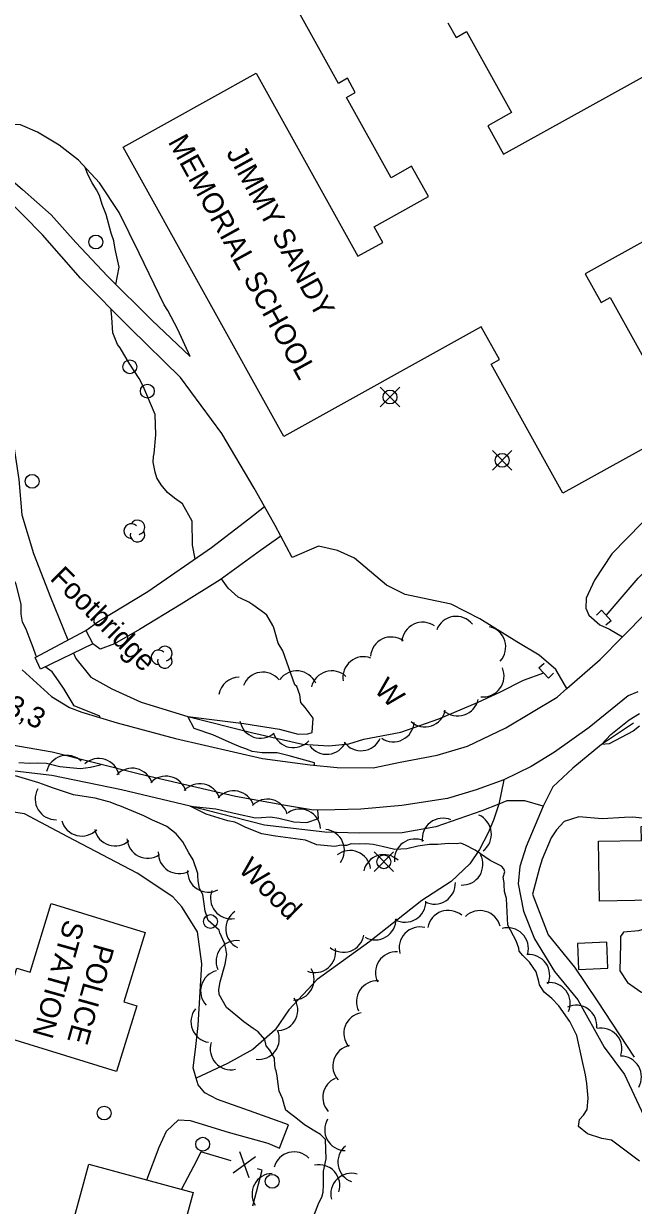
# Model space of a CAD drawing. Extents: x 642515 to 647219, y 6080136 to 6084356.
# Drawn here: x 643658.8 to 643746.7, y 6081698.7 to 6081869.2 of the extents above; entities that cross this region are included whole.
import ezdxf

# ---------------------------------------------------------------- set-up
doc = ezdxf.new("R2010")
doc.units = 0
for name, color, linetype in [('Level 1', 7, 'Continuous'), ('Level 19', 7, 'Continuous'), ('Level 2', 7, 'Continuous'), ('Level 21', 7, 'Continuous'), ('Level 22', 7, 'Continuous'), ('Level 26', 7, 'Continuous'), ('Level 3', 7, 'Continuous'), ('Level 31', 7, 'Continuous'), ('Level 36', 7, 'Continuous'), ('Level 37', 7, 'Continuous'), ('Level 4', 7, 'Continuous'), ('Level 44', 7, 'Continuous'), ('Level 52', 7, 'Continuous')]:
    doc.layers.add(name, color=color, linetype=linetype)

msp = doc.modelspace()

# ---------------------------------------------------------------- linework, layer by layer
at = {"layer": 'Level 1'}
for points in [[(643672.06, 6081831.55), (643672.52, 6081834.03), (643671.95, 6081836.65), (643671.76, 6081837.86), (643671.39, 6081838.95), (643670.65, 6081841.63), (643670.06, 6081843.06), (643669.67, 6081844.39), (643669.27, 6081845.19), (643668.66, 6081846.19), (643668.08, 6081847.3), (643667.63, 6081848.44)], [(643683.49, 6081791.99), (643683.13, 6081793.96), (643683.04, 6081797.42), (643681.67, 6081799.91), (643680.51, 6081800.72), (643679.51, 6081801.53), (643678.57, 6081802.67), (643677.96, 6081803.66), (643677.72, 6081804.47), (643677.44, 6081805.92), (643677.48, 6081806.71), (643677.58, 6081807.15), (643677.84, 6081809.85), (643677.73, 6081812.8), (643676, 6081816.89), (643675.42, 6081818), (643673.99, 6081820.18), (643673.21, 6081821.48), (643672.68, 6081822.4), (643672.29, 6081822.89), (643671.61, 6081824.55), (643671.45, 6081826.79), (643671.36, 6081827.77), (643671.4, 6081827.96)], [(643700.71, 6081762.19), (643700.68, 6081762.54), (643697.07, 6081763.57), (643695.33, 6081763.99), (643695.17, 6081763.98), (643693.14, 6081763.99), (643691.73, 6081764.19), (643690.79, 6081764.58), (643690.1, 6081764.82), (643688.83, 6081765.34), (643686.02, 6081766.57), (643683.37, 6081767.49), (643682.41, 6081769.24), (643690.49, 6081768.21), (643695.64, 6081767.38), (643698.35, 6081766.7), (643699.75, 6081766.73), (643700.38, 6081766.92), (643700.51, 6081768.98), (643699.36, 6081770.53), (643698.72, 6081771.25), (643698.58, 6081772.35), (643698.16, 6081773.54), (643697.87, 6081773.81), (643696.14, 6081778.72), (643695.48, 6081779.83), (643695.14, 6081781.03), (643694.85, 6081782.04), (643694.68, 6081782.35), (643693.84, 6081783.84), (643693.55, 6081784.1), (643691.81, 6081785.35), (643691.23, 6081785.71), (643690.12, 6081786.24), (643689.71, 6081786.46), (643688.25, 6081787.76), (643687.31, 6081789.09)], [(643733.05, 6081731.01), (643732.68, 6081732.39), (643731.7, 6081733.78), (643730.74, 6081734.76), (643730.22, 6081735.37), (643730.15, 6081735.81), (643729.79, 6081736.88), (643728.59, 6081739.13), (643728.41, 6081742.99), (643728.1, 6081744.01), (643728.08, 6081744.94), (643728.06, 6081745.26), (643728.06, 6081745.26), (643727.89, 6081746.07), (643728.13, 6081746.84), (643727.99, 6081747.26), (643727.65, 6081747.64), (643726.06, 6081748.46), (643723.86, 6081749.96), (643722.47, 6081750.67), (643721.82, 6081750.95), (643721.22, 6081750.88), (643719.98, 6081750.93), (643718.47, 6081750.77), (643717.27, 6081750.79), (643715.61, 6081750.54), (643714.03, 6081750.14), (643712.31, 6081750.07), (643710.47, 6081750.47), (643709.16, 6081750.79), (643708.1, 6081750.88), (643707.22, 6081750.82), (643705.97, 6081750.86), (643705.3, 6081750.62), (643704.78, 6081750.62), (643704.57, 6081750.65), (643703.62, 6081750.5), (643701.06, 6081750.7), (643699.41, 6081751.39), (643695.06, 6081751.95), (643693.1, 6081752.31), (643691.74, 6081752.82), (643690.7, 6081753.28), (643689.74, 6081753.74), (643689.2, 6081753.98), (643688.22, 6081754.16), (643685.06, 6081755.12), (643682.77, 6081756.28), (643686.46, 6081755.92), (643689.53, 6081755.2), (643692.19, 6081754.61), (643693.07, 6081754.66)], [(643693.07, 6081754.66), (643694.35, 6081754.75), (643695.54, 6081754.55), (643697.74, 6081754.05), (643699.61, 6081753.93), (643701.26, 6081754.52), (643701.17, 6081755.74)], [(643748.05, 6081754.55), (643746.51, 6081754.7), (643746.51, 6081754.7), (643745.4, 6081754.64), (643742.21, 6081754.47), (643738.84, 6081754.77), (643736.72, 6081754.1), (643735.59, 6081752.86), (643734.85, 6081751.72), (643733.56, 6081748.66), (643733.15, 6081747.38), (643732.14, 6081743.62), (643734.4, 6081737.73), (643738.18, 6081733.07), (643741.49, 6081728.21), (643746.79, 6081720.11)], [(643747.58, 6081705.11), (643743.55, 6081708.1), (643742.12, 6081708.37), (643740.06, 6081709.04), (643738.79, 6081710.09), (643738.92, 6081711.1), (643739.48, 6081711.74), (643740.03, 6081712.54), (643740.16, 6081714.16), (643739.97, 6081716.28), (643739.77, 6081717.52), (643739.36, 6081719.47), (643738.54, 6081723.2), (643737.51, 6081725.22), (643735.95, 6081727.5), (643734.91, 6081728.56), (643733.84, 6081729.49), (643733.16, 6081730.53), (643733.05, 6081731.01)]]:
    msp.add_lwpolyline(points, dxfattribs=at)
at = {"layer": 'Level 19'}
for points in [[(643679.03, 6081828.61), (643675.43, 6081836.08), (643672.53, 6081841.95), (643669.71, 6081846.21), (643666.67, 6081849.46), (643663.89, 6081851.64), (643660.77, 6081853.52), (643658.3, 6081854.59), (643656.61, 6081854.67), (643654.77, 6081854.41), (643652.88, 6081853.67), (643650.76, 6081852.08), (643654.19, 6081849.01), (643658.58, 6081845.24), (643662.73, 6081841.61), (643666.29, 6081837.59), (643670.87, 6081832.74), (643677.22, 6081826.38), (643682.78, 6081821.18), (643680.99, 6081825.06), (643679.55, 6081827.79), (643679.03, 6081828.61)], [(643737.09, 6081773.25), (643735.53, 6081776.01), (643733.12, 6081778.09), (643729.88, 6081780), (643724.54, 6081783.33), (643720.4, 6081785.44), (643716.28, 6081786.31), (643713.76, 6081786.82), (643711.07, 6081788.16), (643706.46, 6081792.05), (643704.03, 6081793.16), (643701.3, 6081793.78), (643697.48, 6081792.18), (643695.86, 6081795.26), (643695.05, 6081796.78), (643693.51, 6081799.5), (643692.01, 6081802.16), (643687.34, 6081810.05), (643681.38, 6081818.12), (643674.1, 6081825.23), (643666.97, 6081832.44), (643661.47, 6081838.72), (643655.92, 6081844.36)], [(643667.7, 6081781.62), (643669.6, 6081782.96), (643676.66, 6081787.25), (643685.83, 6081793.61), (643691.22, 6081797.73), (643693.51, 6081799.5)], [(643750.11, 6081799.36), (643743.57, 6081792.69), (643741.08, 6081788.91), (643739.86, 6081786.28), (643739.82, 6081784.88), (643740.28, 6081783.86), (643741.84, 6081782.46), (643743.25, 6081781.81), (643745.13, 6081780.73)], [(643695.86, 6081795.26), (643692.92, 6081793.18), (643687.12, 6081788.95), (643681.49, 6081785.41), (643675.47, 6081781.78), (643671.85, 6081779.71), (643669.77, 6081778.92), (643668.72, 6081779.71)], [(643754.49, 6081745.61), (643755.21, 6081745.04), (643755.61, 6081743.77), (643754.74, 6081742.09), (643753, 6081739.81), (643750.16, 6081739.13), (643747.44, 6081738.33), (643745.26, 6081738.13), (643744.85, 6081737.5), (643744.83, 6081736.44), (643744.74, 6081732.54), (643745.86, 6081730.85), (643747.77, 6081729.53), (643752.19, 6081727.66), (643755.21, 6081725.47)]]:
    msp.add_lwpolyline(points, dxfattribs=at)
at = {"layer": 'Level 2'}
for points in [[(643660.62, 6081777.87), (643660.53, 6081778.09), (643660.15, 6081779.17), (643659.55, 6081780.68), (643659.1, 6081781.83), (643658.57, 6081782.83), (643658.42, 6081784), (643658.39, 6081785.38), (643657.68, 6081788.33), (643656.63, 6081790.24), (643654.47, 6081799.58), (643653.99, 6081801.96), (643653.52, 6081803.94), (643653.25, 6081805.3), (643652.71, 6081808.03), (643651.56, 6081814.08), (643651.3, 6081815.21), (643650.42, 6081819.97), (643648.85, 6081824.89), (643646.7, 6081832.34), (643643.63, 6081838.45), (643641.72, 6081840.59), (643641.66, 6081841.43)], [(643669.72, 6081769.09), (643669.72, 6081769.26), (643666.05, 6081770.79), (643664.61, 6081773.19), (643663.79, 6081774.37), (643662.85, 6081775.66), (643661.84, 6081776.39)], [(643747.56, 6081767.82), (643746.64, 6081767.12), (643744.93, 6081766.21), (643743.21, 6081765.31), (643742.11, 6081765.18), (643743.46, 6081766.63), (643746.1, 6081768.76), (643747.57, 6081769.66)], [(643658.06, 6081762.59), (643659.63, 6081762.49), (643660.72, 6081762.53), (643662.05, 6081762.49), (643663.97, 6081762.02), (643665.43, 6081761.87), (643666.97, 6081761.73), (643668.4, 6081761.91), (643669.83, 6081762.24), (643669.83, 6081762.32)], [(643695.32, 6081717.39), (643695.19, 6081718.11), (643695.1, 6081718.34), (643694.98, 6081718.9), (643694.91, 6081719.94), (643694.27, 6081721.1), (643693.74, 6081721.71), (643693.52, 6081722.66), (643692.6, 6081723.77), (643691.88, 6081724.24), (643690.53, 6081725.2), (643689.38, 6081726.13), (643688.02, 6081727.25), (643686.96, 6081729.15), (643686.91, 6081729.87), (643687.12, 6081730.97), (643687.83, 6081733.51), (643688.06, 6081734.89), (643687.92, 6081735.76), (643687.71, 6081736.55), (643687.04, 6081738.04), (643686.94, 6081738.43), (643685.35, 6081739.81), (643684.94, 6081741.15), (643684.79, 6081742.19), (643684.62, 6081743.55), (643684.12, 6081744.44), (643683.92, 6081745.51), (643683.87, 6081746.31), (643683.89, 6081746.59), (643683.19, 6081748.56), (643682.56, 6081749.56), (643681.69, 6081751.15), (643680.73, 6081752.29), (643679.41, 6081753.37), (643678.37, 6081753.83), (643677.33, 6081754.28), (643676.08, 6081754.92), (643672.65, 6081756.34), (643672.28, 6081756.44), (643671.21, 6081756.85), (643670.84, 6081756.95), (643669.08, 6081757.44), (643668.1, 6081757.61), (643665.95, 6081757.91), (643662.9, 6081758.92), (643662, 6081759.26), (643660.96, 6081759.64), (643657.56, 6081760.66)], [(643700.6, 6081697.2), (643701.35, 6081699.09), (643701.74, 6081699.88), (643701.93, 6081700.62), (643702.02, 6081701.67), (643702.01, 6081703.64), (643702.37, 6081705.43), (643702.3, 6081708.2), (643701.57, 6081708.92), (643700.73, 6081709.43), (643699.26, 6081710.34), (643698.03, 6081711.34), (643697.26, 6081711.93), (643696.58, 6081712.45), (643696.38, 6081713.08), (643696.07, 6081714.11), (643695.59, 6081715.2), (643695.42, 6081716.56), (643695.32, 6081717.39)]]:
    msp.add_lwpolyline(points, dxfattribs=at)
at = {"layer": 'Level 21'}
for points in [[(643658.54, 6081775.96), (643662.77, 6081772.11), (643665.39, 6081770.52), (643667.16, 6081769.86), (643672.26, 6081768.32), (643680.65, 6081766.04), (643693.19, 6081763.18), (643700.07, 6081762.26), (643703.99, 6081761.86), (643709.14, 6081761.81), (643713.07, 6081762.62), (643718.37, 6081763.65), (643722.76, 6081764.96), (643728.28, 6081767.61), (643735.68, 6081772.01), (643737.09, 6081773.25), (643741.89, 6081777.46), (643745.13, 6081780.73), (643748.6, 6081784.22), (643756.35, 6081793.16), (643766.55, 6081805.08), (643776.58, 6081816.72), (643784.32, 6081827.51)], [(643747.33, 6081772.79), (643745.95, 6081772.2), (643740.33, 6081767.66), (643735.34, 6081764.08), (643731.96, 6081762.02), (643728, 6081760.09), (643724.02, 6081758.64), (643719.87, 6081757.42), (643713.29, 6081756.4), (643707.37, 6081755.85), (643703.64, 6081755.77)], [(643703.64, 6081755.77), (643700.54, 6081755.73), (643696.51, 6081756.41), (643689.31, 6081757.71), (643675.46, 6081760.91), (643662.87, 6081764.07), (643657.04, 6081765.09)]]:
    msp.add_lwpolyline(points, dxfattribs=at)
at = {"layer": 'Level 22'}
msp.add_lwpolyline([(643728, 6081760.09), (643727.29, 6081756.59), (643726.5, 6081754.27), (643725.75, 6081752.43), (643724.52, 6081750.04), (643723.11, 6081747.97), (643720.41, 6081745.42), (643716.18, 6081742.68), (643708.66, 6081736.76), (643701.07, 6081731.29), (643697, 6081726.9), (643695.01, 6081724.02), (643691.81, 6081721.22), (643688.15, 6081719.2), (643685.06, 6081717.75), (643683.65, 6081717.07)], dxfattribs=at)
at = {"layer": 'Level 26'}
for p, q in [((643742.09, 6081784.55), (643741.35, 6081783.87)), ((643742.09, 6081784.55), (643743.47, 6081783.05)), ((643743.47, 6081783.05), (643742.73, 6081782.39)), ((643733.07, 6081776.26), (643733.81, 6081776.94)), ((643734.45, 6081774.78), (643733.07, 6081776.26)), ((643734.45, 6081774.78), (643735.19, 6081775.46))]:
    msp.add_line(p, q, dxfattribs=at)
msp.add_lwpolyline([(643668.72, 6081779.71), (643661.18, 6081776.08), (643660.4, 6081777.75), (643667.7, 6081781.62), (643668.72, 6081779.71)], dxfattribs=at)
at = {"layer": 'Level 31'}
for points in [[(643724.72, 6081825.43), (643696.26, 6081809.64), (643673.11, 6081851.37), (643692.31, 6081862.03), (643706.97, 6081835.61), (643710.56, 6081837.6), (643709.29, 6081839.87), (643717.13, 6081844.22), (643714.7, 6081848.59), (643711.74, 6081846.95), (643705.31, 6081858.53), (643706.59, 6081859.24), (643705.46, 6081861.29), (643704.15, 6081860.56), (643693.83, 6081879.17)], [(643719.94, 6081869.29), (643721.11, 6081867.19), (643722.63, 6081868.03), (643729.12, 6081856.33), (643725.68, 6081854.42), (643727.94, 6081850.34), (643749.38, 6081862.24), (643750.01, 6081861.11), (643753.38, 6081862.98), (643761.04, 6081849.17), (643757.62, 6081847.27), (643759.42, 6081844.02), (643739.76, 6081833.1), (643742.06, 6081828.95), (643743.36, 6081829.67), (643753.73, 6081810.98), (643736.53, 6081801.44), (643726.19, 6081820.07), (643727.36, 6081820.72), (643724.72, 6081825.43)], [(643754.54, 6081742.83), (643741.81, 6081742.61), (643741.66, 6081751.25), (643747.86, 6081751.36), (643747.83, 6081753.38), (643750.79, 6081753.43), (643750.82, 6081751.56), (643754.38, 6081751.62), (643754.54, 6081742.83)], [(643672.15, 6081718.02), (643654.83, 6081723.36), (643657.79, 6081732.94), (643659.69, 6081732.35), (643662.74, 6081742.25), (643676.29, 6081738.07), (643673.21, 6081728.08), (643675.07, 6081727.51), (643672.15, 6081718.02)], [(643742.84, 6081736.68), (643738.61, 6081736.47), (643738.79, 6081732.74), (643743.02, 6081732.94), (643742.84, 6081736.68)], [(643652.54, 6081649.31), (643662.41, 6081685.52), (643662.91, 6081685.38), (643668.17, 6081704.66), (643683.18, 6081700.57), (643677.8, 6081680.82), (643678.3, 6081680.69), (643671.66, 6081656.31), (643673.57, 6081655.79), (643670.43, 6081644.3), (643652.54, 6081649.31)]]:
    msp.add_lwpolyline(points, dxfattribs=at)
at = {"layer": 'Level 36'}
for p, q in [((643713, 6081813.9), (643710.18, 6081816.72)), ((643710.18, 6081813.9), (643713, 6081816.72)), ((643729.18, 6081804.77), (643726.36, 6081807.59)), ((643726.36, 6081804.77), (643729.18, 6081807.59)), ((643712.11, 6081746.87), (643709.29, 6081749.69)), ((643709.29, 6081746.87), (643712.11, 6081749.69))]:
    msp.add_line(p, q, dxfattribs=at)
for centre in [(643669.17, 6081837.67), (643674.06, 6081819.68), (643676.6, 6081816.15), (643711.59, 6081815.31), (643727.77, 6081806.18), (643659.97, 6081803.15), (643710.7, 6081748.28), (643685.69, 6081739.65), (643670.36, 6081712.03), (643684.58, 6081707.53), (643694.61, 6081702.18)]:
    msp.add_circle(centre, 1, dxfattribs=at)
at = {"layer": 'Level 37'}
for p, q in [((643688.98, 6081703.39), (643692.2, 6081705.76)), ((643691.28, 6081702.69), (643689.91, 6081706.45)), ((643683.66, 6081705.16), (643681.51, 6081701.03))]:
    msp.add_line(p, q, dxfattribs=at)
for points in [[(643688.67, 6081705.15), (643684.33, 6081706.46), (643683.66, 6081705.16)], [(643691.83, 6081698.65), (643693.16, 6081703.79), (643692.5, 6081703.99)]]:
    msp.add_lwpolyline(points, dxfattribs=at)
at = {"layer": 'Level 4'}
for points in [[(643742.77, 6081783.81), (643747.38, 6081789.18), (643754.14, 6081795.75), (643760.81, 6081803.32), (643766.41, 6081809.88), (643771.94, 6081816.87), (643777.98, 6081825.01), (643780.66, 6081829.01), (643782.96, 6081832.67), (643786.67, 6081838.41), (643788.93, 6081842.18), (643791.84, 6081847.8), (643794.06, 6081853.07), (643795.93, 6081857.19), (643799.09, 6081863.51), (643801.55, 6081869.4)], [(643645.11, 6081840.32), (643648.77, 6081833.86), (643651.48, 6081827.19), (643654.21, 6081817.32), (643657.03, 6081810.11), (643658.05, 6081803.43), (643658.5, 6081798.33), (643660.18, 6081792.74), (643662.62, 6081786.46), (643665.14, 6081780.27)], [(643665.94, 6081778.37), (643666.26, 6081777.6), (643668.42, 6081774.91), (643671.49, 6081773.23), (643675.7, 6081771.29), (643682.41, 6081769.24), (643691.82, 6081766.89), (643698.95, 6081765.22), (643702.75, 6081765.02), (643705.67, 6081765.29), (643707.8, 6081765.96), (643713.14, 6081766.96), (643718.63, 6081768.89), (643724.21, 6081771.27), (643727.55, 6081772.77), (643730.84, 6081774.46), (643733.77, 6081775.52)], [(643746.73, 6081768.27), (643742.11, 6081765.18), (643737.95, 6081761.76), (643735.08, 6081759.08), (643733.67, 6081756.32), (643731.25, 6081750.5), (643730.33, 6081747.61), (643730.07, 6081745.11), (643730.84, 6081741.16), (643732.41, 6081737.14), (643735.3, 6081732.47), (643738.69, 6081728.37), (643742.5, 6081721.54), (643745.43, 6081717.6), (643748.54, 6081710.93)], [(643733.67, 6081756.32), (643731.05, 6081757.07), (643728.43, 6081757.05), (643727.29, 6081756.59), (643724.85, 6081755.62), (643718.18, 6081753.31), (643713.36, 6081752.46), (643707.2, 6081752.41), (643702.18, 6081752.56), (643693.5, 6081753.56), (643682.77, 6081756.28), (643672.87, 6081758.66), (643662.84, 6081760.7), (643656.66, 6081761.42), (643653.51, 6081761.45), (643652.53, 6081761.1), (643651.74, 6081760.12), (643650.31, 6081756.84), (643648.16, 6081750.24)]]:
    msp.add_lwpolyline(points, dxfattribs=at)
at = {"layer": 'Level 44'}
for centre, radius, start, end in [((643675.17, 6081796.51), 1.05, 282.2692, 149.7263), ((643674.27, 6081795.98), 1.05, 44.1154, 269.804), ((643675.17, 6081795.46), 1.05, 166.9369, 29.6212), ((643721.13, 6081780.67), 3, 38.8188, 158.7967), ((643716.3, 6081779.83), 3, 55.2991, 175.277), ((643725.28, 6081779.25), 3, 317.715, 77.6929), ((643711.78, 6081777.7), 3, 55.2991, 175.277), ((643678.21, 6081777.78), 1.05, 44.1154, 269.804), ((643679.11, 6081778.31), 1.05, 282.2692, 149.7263), ((643679.11, 6081777.26), 1.05, 166.9369, 29.6212), ((643707.79, 6081774.86), 3, 69.3818, 189.3597), ((643693.26, 6081772.63), 3, 38.7001, 158.678), ((643698.14, 6081772.81), 3, 24.4514, 144.4294), ((643703.19, 6081772.82), 3, 47.0796, 167.0576), ((643725.04, 6081775.06), 3, 263.2005, 23.1784), ((643689.88, 6081771.91), 3, 90.3838, 170.4321), ((643721.37, 6081772.3), 3, 228.2959, 348.2739), ((643716.62, 6081770.73), 3, 228.2959, 348.2739), ((643692.9, 6081769.1), 3, 190.8301, 310.808), ((643712.07, 6081768.58), 3, 236.3598, 356.3377), ((643697.66, 6081767.74), 3, 197.7148, 317.6927), ((643702.46, 6081766.78), 3, 215.8462, 335.8242), ((643707.43, 6081767.29), 3, 215.8462, 335.8242), ((643664.98, 6081760.62), 3, 46.6133, 166.5912), ((643669.58, 6081760.17), 3, 12.2767, 132.2546), ((643674.4, 6081758.77), 3, 16.8576, 136.8356), ((643679.27, 6081757.63), 3, 16.8576, 136.8356), ((643663.41, 6081757.34), 3, 151.2748, 271.2527), ((643684.15, 6081756.54), 3, 18.1182, 138.0961), ((643689.05, 6081755.51), 3, 18.1182, 138.0961), ((643693.89, 6081754.31), 3, 15.6687, 135.6467), ((643698.59, 6081752.87), 3, 4.2313, 124.2093), ((643723.22, 6081752.26), 3, 306.612, 66.5899), ((643667.13, 6081754.99), 3, 196.0425, 316.0204), ((643671.94, 6081753.56), 3, 191.9499, 311.9278), ((643702.02, 6081749.95), 3, 323.8601, 83.838), ((643719.23, 6081751.56), 3, 67.3068, 187.2847), ((643676.65, 6081751.79), 3, 184.0064, 303.9844), ((643715.22, 6081748.56), 3, 65.6918, 185.6697), ((643681.17, 6081749.57), 3, 177.6132, 297.5911), ((643705.83, 6081746.9), 3, 8.0483, 128.0263), ((643710.72, 6081746.3), 3, 47.2018, 167.1798), ((643722, 6081747.92), 3, 267.2966, 27.2745), ((643685.39, 6081746.89), 3, 177.6132, 297.5911), ((643718.02, 6081745.17), 3, 242.607, 2.585), ((643688.7, 6081743.05), 3, 158.7159, 278.6938), ((643690.91, 6081738.6), 3, 123.9341, 243.912), ((643713.77, 6081742.56), 3, 240.6986, 0.6766), ((643719.99, 6081738.27), 3, 49.5851, 169.5631), ((643724.57, 6081738.24), 3, 14.2168, 134.1947), ((643709.47, 6081740.01), 3, 240.6986, 0.6766), ((643704.87, 6081738.22), 3, 229.9044, 349.8823), ((643715.91, 6081735.87), 3, 76.0244, 196.0023), ((643728.55, 6081735.76), 3, 345.1139, 105.0918), ((643689.51, 6081733.91), 3, 83.1076, 203.0856), ((643700.76, 6081735.29), 3, 249.5715, 9.5494), ((643712.5, 6081732.29), 3, 86.7439, 206.7218), ((643731.63, 6081731.9), 3, 335.4402, 95.4182), ((643687.27, 6081729.64), 3, 103.4023, 223.3802), ((643697.65, 6081731.33), 3, 270.3001, 30.2781), ((643709.75, 6081728.11), 3, 86.7439, 206.7218), ((643734.59, 6081727.86), 3, 336.9468, 96.9247), ((643695.29, 6081726.91), 3, 274.5449, 34.5229), ((643738.43, 6081724.59), 3, 354.4494, 114.4273), ((643685.88, 6081725.2), 3, 141.5134, 261.4913), ((643707.93, 6081723.54), 3, 99.6695, 219.6474), ((643692.63, 6081722.77), 3, 263.2823, 23.2602), ((643742.05, 6081721.28), 3, 342.1049, 102.0828), ((643688.66, 6081721.27), 3, 162.1826, 282.1605), ((643706.34, 6081718.82), 3, 102.3189, 222.2968), ((643744.86, 6081717.25), 3, 330.127, 90.105), ((643704.9, 6081714.28), 3, 113.6002, 222.5884), ((643705.17, 6081709.62), 3, 149.0911, 269.069), ((643707.07, 6081704.96), 3, 129.7217, 249.6997), ((643697.77, 6081703.43), 3, 44.7086, 164.6866), ((643701.36, 6081701.58), 3, 342.295, 102.273), ((643694.69, 6081700.33), 3, 92.1183, 212.0963), ((643706.04, 6081700.34), 3, 74.1489, 194.1268)]:
    msp.add_arc(centre, radius, start, end, dxfattribs=at)
at = {"layer": 'Level 52'}
msp.add_lwpolyline([(643676.54, 6081702.38), (643678.28, 6081707.13), (643679.38, 6081709.42), (643681.09, 6081711.03), (643682.75, 6081710.94), (643688.26, 6081709.29), (643693.96, 6081707.69), (643695.67, 6081706.96), (643696.97, 6081710.35), (643692.02, 6081712.12), (643686.69, 6081713.99), (643684.89, 6081714.96), (643683.93, 6081716.1), (643683.65, 6081717.07), (643683.21, 6081718.55), (643683.55, 6081721.2), (643683.93, 6081724.66), (643684.47, 6081733.57), (643683.81, 6081738.17), (643681.59, 6081741.77), (643680.29, 6081743.22), (643675.11, 6081746.62), (643665.12, 6081751.89), (643658.86, 6081755.18), (643655.69, 6081755.69)], dxfattribs=at)

# ---------------------------------------------------------------- texts
at = {"layer": 'Level 26'}
msp.add_text('Footbridge', height=3, rotation=315.1749, dxfattribs=at).set_placement((643662.44, 6081789.03))
at = {"layer": 'Level 3'}
msp.add_text('493,3', height=3, rotation=332.7168, dxfattribs=at).set_placement((643651.97, 6081771.9))
at = {"layer": 'Level 31'}
for s, rotation, p in [('MEMORIAL SCHOOL', 298.8171, (643679.51, 6081852.14)), ('JIMMY SANDY', 298.8171, (643687.91, 6081850.53)), ('STATION', 254.3808, (643664.68, 6081740.1)), ('POLICE', 254.3808, (643668.98, 6081736.63))]:
    msp.add_text(s, height=3, rotation=rotation, dxfattribs=at).set_placement(p)
at = {"layer": 'Level 44'}
for s, p in [('W', (643709.15, 6081772.96)), ('Wood', (643689.58, 6081747.06))]:
    msp.add_text(s, height=3, rotation=315.1749, dxfattribs=at).set_placement(p)

doc.saveas('drawing.dxf')
